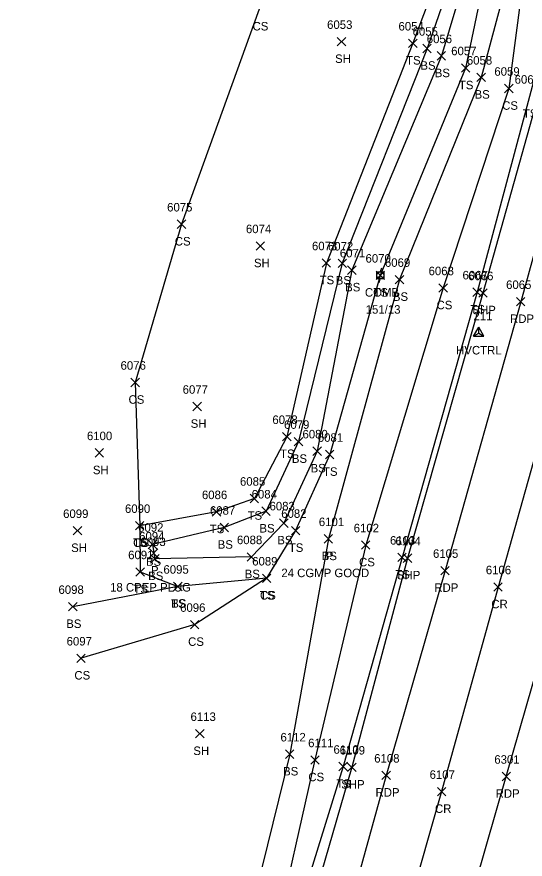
# Model space of a CAD drawing. Extents: x 1443912 to 1445411, y 621446 to 623693.
# Drawn here: x 1444411.3 to 1444530.8, y 621732.1 to 621930 of the extents above; entities that cross this region are included whole.
import ezdxf

# ---------------------------------------------------------------- set-up
doc = ezdxf.new("R2010")
doc.units = 0
for name, color, linetype in [('C_A', 7, 'Continuous'), ('C_I', 7, 'Continuous'), ('CPSM', 7, 'Continuous'), ('D_A', 7, 'Continuous'), ('D_C', 7, 'Continuous'), ('D_I', 7, 'Continuous'), ('D_TIC', 7, 'Continuous'), ('L_A', 7, 'Continuous'), ('L_I', 7, 'Continuous'), ('L_TIC', 7, 'Continuous'), ('LELB', 7, 'Continuous'), ('P_A', 7, 'Continuous'), ('P_I', 7, 'Continuous'), ('P_TIC', 7, 'Continuous'), ('PET', 7, 'Continuous'), ('PRC', 7, 'Continuous'), ('PSP', 7, 'Continuous'), ('U_A', 7, 'Continuous'), ('U_C', 7, 'Continuous'), ('U_I', 7, 'Continuous'), ('UP', 7, 'Continuous')]:
    doc.layers.add(name, color=color, linetype=linetype)

msp = doc.modelspace()

# ---------------------------------------------------------------- linework, layer by layer
at = {"layer": 'CPSM'}
for p, q in [((1444518.66, 621854.96), (1444519.91, 621857.13)), ((1444521.16, 621854.96), (1444519.91, 621857.13)), ((1444519.91, 621855.68), (1444519.91, 621857.13)), ((1444518.66, 621854.96), (1444519.91, 621855.68)), ((1444518.66, 621854.96), (1444521.16, 621854.96)), ((1444519.91, 621855.68), (1444519.91, 621855.68)), ((1444519.91, 621855.68), (1444521.16, 621854.96))]:
    msp.add_line(p, q, dxfattribs=at)
at = {"layer": 'D_TIC'}
for points in [[(1444483.56, 621806.34), (1444485.56, 621808.34)], [(1444485.56, 621806.34), (1444483.56, 621808.34)], [(1444442.45, 621802.96), (1444444.45, 621804.96)], [(1444444.45, 621802.96), (1444442.45, 621804.96)]]:
    msp.add_lwpolyline(points, dxfattribs=at)
at = {"layer": 'L_TIC'}
for points in [[(1444486.65, 621923.19), (1444488.65, 621925.19)], [(1444488.65, 621923.19), (1444486.65, 621925.19)], [(1444503.44, 621922.81), (1444505.44, 621924.81)], [(1444505.44, 621922.81), (1444503.44, 621924.81)], [(1444506.76, 621921.59), (1444508.76, 621923.59)], [(1444508.76, 621921.59), (1444506.76, 621923.59)], [(1444510.14, 621919.84), (1444512.14, 621921.84)], [(1444512.14, 621919.84), (1444510.14, 621921.84)], [(1444515.84, 621917), (1444517.84, 621919)], [(1444517.84, 621917), (1444515.84, 621919)], [(1444519.51, 621914.8), (1444521.51, 621916.8)], [(1444521.51, 621914.8), (1444519.51, 621916.8)], [(1444526, 621912.18), (1444528, 621914.18)], [(1444528, 621912.18), (1444526, 621914.18)], [(1444449.01, 621880.28), (1444451.01, 621882.28)], [(1444451.01, 621880.28), (1444449.01, 621882.28)], [(1444467.56, 621875.18), (1444469.56, 621877.18)], [(1444469.56, 621875.18), (1444467.56, 621877.18)], [(1444483.09, 621871.17), (1444485.09, 621873.17)], [(1444485.09, 621871.17), (1444483.09, 621873.17)], [(1444486.84, 621871.1), (1444488.84, 621873.1)], [(1444488.84, 621871.1), (1444486.84, 621873.1)], [(1444489.07, 621869.5), (1444491.07, 621871.5)], [(1444491.07, 621869.5), (1444489.07, 621871.5)], [(1444495.77, 621868.26), (1444497.77, 621870.26)], [(1444497.77, 621868.26), (1444495.77, 621870.26)], [(1444500.3, 621867.27), (1444502.3, 621869.27)], [(1444502.3, 621867.27), (1444500.3, 621869.27)], [(1444510.56, 621865.3), (1444512.56, 621867.3)], [(1444512.56, 621865.3), (1444510.56, 621867.3)], [(1444518.55, 621864.32), (1444520.55, 621866.32)], [(1444520.55, 621864.32), (1444518.55, 621866.32)], [(1444438.12, 621843.09), (1444440.12, 621845.09)], [(1444440.12, 621843.09), (1444438.12, 621845.09)], [(1444452.68, 621837.44), (1444454.68, 621839.44)], [(1444454.68, 621837.44), (1444452.68, 621839.44)], [(1444473.78, 621830.34), (1444475.78, 621832.34)], [(1444475.78, 621830.34), (1444473.78, 621832.34)], [(1444476.53, 621829.2), (1444478.53, 621831.2)], [(1444478.53, 621829.2), (1444476.53, 621831.2)], [(1444429.69, 621826.54), (1444431.69, 621828.54)], [(1444431.69, 621826.54), (1444429.69, 621828.54)], [(1444480.94, 621826.95), (1444482.94, 621828.95)], [(1444482.94, 621826.95), (1444480.94, 621828.95)], [(1444483.88, 621826.15), (1444485.88, 621828.15)], [(1444485.88, 621826.15), (1444483.88, 621828.15)], [(1444466.15, 621815.83), (1444468.15, 621817.83)], [(1444468.15, 621815.83), (1444466.15, 621817.83)], [(1444457.26, 621812.68), (1444459.26, 621814.68)], [(1444459.26, 621812.68), (1444457.26, 621814.68)], [(1444468.9, 621812.83), (1444470.9, 621814.83)], [(1444470.9, 621812.83), (1444468.9, 621814.83)], [(1444439.19, 621809.44), (1444441.19, 621811.44)], [(1444441.19, 621809.44), (1444439.19, 621811.44)], [(1444439.19, 621809.44), (1444441.19, 621811.44)], [(1444441.19, 621809.44), (1444439.19, 621811.44)], [(1444459.08, 621809.02), (1444461.08, 621811.02)], [(1444461.08, 621809.02), (1444459.08, 621811.02)], [(1444473.1, 621810.04), (1444475.1, 621812.04)], [(1444475.1, 621810.04), (1444473.1, 621812.04)], [(1444424.57, 621808.25), (1444426.57, 621810.25)], [(1444426.57, 621808.25), (1444424.57, 621810.25)], [(1444475.85, 621808.28), (1444477.85, 621810.28)], [(1444477.85, 621808.28), (1444475.85, 621810.28)], [(1444442.21, 621805.01), (1444444.21, 621807.01)], [(1444444.21, 621805.01), (1444442.21, 621807.01)], [(1444483.56, 621806.34), (1444485.56, 621808.34)], [(1444485.56, 621806.34), (1444483.56, 621808.34)], [(1444492.34, 621804.88), (1444494.34, 621806.88)], [(1444494.34, 621804.88), (1444492.34, 621806.88)], [(1444442.74, 621801.65), (1444444.74, 621803.65)], [(1444444.74, 621801.65), (1444442.74, 621803.65)], [(1444442.74, 621801.65), (1444444.74, 621803.65)], [(1444444.74, 621801.65), (1444442.74, 621803.65)], [(1444465.44, 621802.09), (1444467.44, 621804.09)], [(1444467.44, 621802.09), (1444465.44, 621804.09)], [(1444500.88, 621801.99), (1444502.88, 621803.99)], [(1444502.88, 621801.99), (1444500.88, 621803.99)], [(1444439.29, 621798.56), (1444441.29, 621800.56)], [(1444441.29, 621798.56), (1444439.29, 621800.56)], [(1444469.04, 621797.08), (1444471.04, 621799.08)], [(1444471.04, 621797.08), (1444469.04, 621799.08)], [(1444469.04, 621797.08), (1444471.04, 621799.08)], [(1444471.04, 621797.08), (1444469.04, 621799.08)], [(1444448.16, 621795.15), (1444450.16, 621797.15)], [(1444450.16, 621795.15), (1444448.16, 621797.15)], [(1444448.16, 621795.15), (1444450.16, 621797.15)], [(1444450.16, 621795.15), (1444448.16, 621797.15)], [(1444448.16, 621795.15), (1444450.16, 621797.15)], [(1444450.16, 621795.15), (1444448.16, 621797.15)], [(1444423.47, 621790.4), (1444425.47, 621792.4)], [(1444425.47, 621790.4), (1444423.47, 621792.4)], [(1444452.13, 621786.19), (1444454.13, 621788.19)], [(1444454.13, 621786.19), (1444452.13, 621788.19)], [(1444425.38, 621778.28), (1444427.38, 621780.28)], [(1444427.38, 621778.28), (1444425.38, 621780.28)], [(1444453.31, 621760.54), (1444455.31, 621762.54)], [(1444455.31, 621760.54), (1444453.31, 621762.54)], [(1444474.47, 621755.73), (1444476.47, 621757.73)], [(1444476.47, 621755.73), (1444474.47, 621757.73)], [(1444480.4, 621754.38), (1444482.4, 621756.38)], [(1444482.4, 621754.38), (1444480.4, 621756.38)], [(1444487.02, 621752.84), (1444489.02, 621754.84)], [(1444489.02, 621752.84), (1444487.02, 621754.84)]]:
    msp.add_lwpolyline(points, dxfattribs=at)
at = {"layer": 'LELB'}
for points in [[(1444632.65, 622301.98), (1444621.14, 622262.03), (1444607.9, 622216.16), (1444601.86, 622188.05), (1444585.99, 622134.3), (1444576.44, 622101.07), (1444565.66, 622076.68), (1444562.93, 622059.13), (1444545.54, 622046.15), (1444545.6, 622027.09), (1444542.78, 622003.02), (1444539.57, 621991.69), (1444533.95, 621966.13), (1444520.51, 621915.8), (1444501.3, 621868.27), (1444484.56, 621807.34), (1444475.47, 621756.73), (1444466.25, 621719.25), (1444448.38, 621716.17)], [(1444525.06, 622097.11), (1444514.69, 622074.67), (1444511.07, 622042.48), (1444501.15, 622010.66), (1444490.92, 621981.5), (1444468.29, 621931.82), (1444450.01, 621881.28), (1444439.12, 621844.09), (1444440.19, 621810.44)], [(1444574.55, 622074.53), (1444566.78, 622059.21), (1444562.93, 622059.13), (1444561.5, 622033.21), (1444553.8, 621993.71), (1444545.42, 621962.05), (1444531.89, 621911.31), (1444519.55, 621865.32), (1444501.88, 621802.99), (1444488.02, 621753.84), (1444471.78, 621701.48), (1444460.31, 621656.88), (1444459.55, 621655.45), (1444452.09, 621632.21), (1444445.68, 621624.35), (1444438.52, 621621.89)], [(1444527.32, 621968.25), (1444521.77, 621969.91), (1444504.44, 621923.81), (1444484.09, 621872.17), (1444474.78, 621831.34), (1444467.15, 621816.83), (1444458.26, 621813.68), (1444440.19, 621810.44), (1444440.29, 621799.56), (1444449.16, 621796.15)], [(1444525.1, 621967.65), (1444523.49, 621967.86), (1444507.76, 621922.59), (1444487.84, 621872.1), (1444477.53, 621830.2), (1444469.9, 621813.83), (1444460.08, 621810.02), (1444443.21, 621806.01), (1444443.74, 621802.65)], [(1444525.1, 621967.65), (1444511.14, 621920.84), (1444490.07, 621870.5), (1444481.94, 621827.95), (1444474.1, 621811.04), (1444466.44, 621803.09), (1444443.74, 621802.65)], [(1444527.32, 621968.25), (1444516.84, 621918), (1444496.77, 621869.26), (1444484.88, 621827.15), (1444476.85, 621809.28), (1444470.04, 621798.08), (1444449.16, 621796.15)], [(1444533.95, 621966.13), (1444527, 621913.18), (1444511.56, 621866.3), (1444493.34, 621805.88), (1444481.4, 621755.38), (1444471.56, 621711.89), (1444462.68, 621687.59)], [(1444470.04, 621798.08), (1444453.13, 621787.19), (1444426.38, 621779.28)], [(1444449.16, 621796.15), (1444424.47, 621791.4)]]:
    msp.add_lwpolyline(points, dxfattribs=at)
at = {"layer": 'P_TIC'}
for points in [[(1444519.92, 621864.12), (1444521.92, 621866.12)], [(1444521.92, 621864.12), (1444519.92, 621866.12)], [(1444528.8, 621862.07), (1444530.8, 621864.07)], [(1444530.8, 621862.07), (1444528.8, 621864.07)], [(1444502.16, 621801.82), (1444504.16, 621803.82)], [(1444504.16, 621801.82), (1444502.16, 621803.82)], [(1444510.99, 621798.88), (1444512.99, 621800.88)], [(1444512.99, 621798.88), (1444510.99, 621800.88)], [(1444523.46, 621795.02), (1444525.46, 621797.02)], [(1444525.46, 621795.02), (1444523.46, 621797.02)], [(1444489.06, 621752.65), (1444491.06, 621754.65)], [(1444491.06, 621752.65), (1444489.06, 621754.65)], [(1444497.16, 621750.76), (1444499.16, 621752.76)], [(1444499.16, 621750.76), (1444497.16, 621752.76)], [(1444525.41, 621750.49), (1444527.41, 621752.49)], [(1444527.41, 621750.49), (1444525.41, 621752.49)], [(1444510.19, 621746.94), (1444512.19, 621748.94)], [(1444512.19, 621746.94), (1444510.19, 621748.94)]]:
    msp.add_lwpolyline(points, dxfattribs=at)
at = {"layer": 'PET'}
for points in [[(1444707.78, 622511.05), (1444700.03, 622482.58), (1444691.73, 622453.67), (1444679.73, 622411.23), (1444667.69, 622368.84), (1444653.08, 622317.67), (1444637.74, 622256.92), (1444626.42, 622209.58), (1444619.02, 622182.67), (1444605.37, 622130.08), (1444589.4, 622078.61), (1444578.44, 622026.86), (1444565.52, 621990.05), (1444556.87, 621958.17), (1444542.16, 621907.74), (1444529.8, 621863.07), (1444511.99, 621799.88), (1444498.16, 621751.76), (1444483.13, 621697.3), (1444470.84, 621653.16), (1444463.41, 621627.34), (1444449.07, 621575.52), (1444430.26, 621508.83), (1444421.17, 621471.46)], [(1444444.37, 621464.94), (1444461.94, 621522.87), (1444475.59, 621570.55), (1444487.99, 621616.26), (1444502.92, 621667.73), (1444516.83, 621718.16), (1444526.41, 621751.49), (1444537.28, 621789.32), (1444558.59, 621865), (1444573.59, 621917.93), (1444597.58, 621998.81), (1444610.14, 622044.19), (1444623.48, 622089.5), (1444632.2, 622118.09)]]:
    msp.add_lwpolyline(points, dxfattribs=at)
at = {"layer": 'PRC'}
msp.add_lwpolyline([(1444618.32, 622127.38), (1444604.97, 622075.74), (1444590.11, 622023.77), (1444578.57, 621985.29), (1444569.73, 621954.72), (1444555.25, 621903.96), (1444542.35, 621859.58), (1444524.46, 621796.02), (1444511.19, 621747.94), (1444495.68, 621693.61), (1444483.2, 621649.28), (1444475.93, 621623.97), (1444461.82, 621572.2), (1444443.22, 621505.41), (1444432.75, 621467.94)], dxfattribs=at)
at = {"layer": 'PSP'}
msp.add_lwpolyline([(1444596.17, 622132.46), (1444585.6, 622096.58), (1444576.22, 622067.8), (1444567.15, 622029.85), (1444556.7, 621993.22), (1444548.18, 621960.88), (1444533.68, 621910.62), (1444520.92, 621865.12), (1444503.16, 621802.82), (1444490.06, 621753.65), (1444474.75, 621700.87), (1444461.97, 621656.27), (1444456.61, 621636.09), (1444438.52, 621570.3), (1444424.57, 621519.38), (1444411.29, 621473.11)], dxfattribs=at)
at = {"layer": 'UP'}
for p, q in [((1444495.94, 621868.43), (1444495.94, 621870.1)), ((1444495.94, 621870.1), (1444497.61, 621870.1)), ((1444497.02, 621870.93), (1444496.77, 621870.1)), ((1444497.61, 621870.1), (1444497.61, 621868.43)), ((1444497.61, 621868.43), (1444495.94, 621868.43)), ((1444496.52, 621867.6), (1444496.77, 621868.43)), ((1444496.77, 621869.26), (1444496.77, 621869.26))]:
    msp.add_line(p, q, dxfattribs=at)
msp.add_circle((1444496.77, 621869.26), 0.833, dxfattribs=at)

# ---------------------------------------------------------------- texts
at = {"layer": 'C_A'}
msp.add_text('HVCTRL', height=2, dxfattribs=at).set_placement((1444514.61, 621850.68))
at = {"layer": 'C_I'}
msp.add_text('211', height=2, dxfattribs=at).set_placement((1444518.68, 621858.68))
at = {"layer": 'D_A'}
for p in [(1444483.94, 621802.34), (1444442.83, 621798.96)]:
    msp.add_text('P', height=2, dxfattribs=at).set_placement(p)
at = {"layer": 'D_C'}
for s, p in [('24 CGMP GOOD', (1444473.5, 621798.34)), ('18 CPEP PLUG', (1444433.22, 621794.96))]:
    msp.add_text(s, height=2, dxfattribs=at).set_placement(p)
at = {"layer": 'D_I'}
for s, p in [('6101', (1444482.31, 621810.34)), ('6094', (1444440.06, 621806.96))]:
    msp.add_text(s, height=2, dxfattribs=at).set_placement(p)
at = {"layer": 'L_A'}
for s, p in [('CS', (1444466.73, 621926.82)), ('SH', (1444486.14, 621919.19)), ('TS', (1444502.85, 621918.81)), ('BS', (1444506.2, 621917.59)), ('BS', (1444509.58, 621915.84)), ('TS', (1444515.25, 621913)), ('BS', (1444518.95, 621910.8)), ('CS', (1444525.44, 621908.18)), ('TS', (1444530.3, 621906.31)), ('CS', (1444448.45, 621876.28)), ('SH', (1444467.05, 621871.18)), ('TS', (1444482.5, 621867.17)), ('BS', (1444486.28, 621867.1)), ('BS', (1444488.51, 621865.5)), ('TS', (1444495.18, 621864.26)), ('BS', (1444499.74, 621863.27)), ('CS', (1444510.01, 621861.3)), ('TS', (1444517.96, 621860.32)), ('CS', (1444437.56, 621839.09)), ('SH', (1444452.17, 621833.44)), ('TS', (1444473.19, 621826.34)), ('BS', (1444475.98, 621825.2)), ('SH', (1444429.17, 621822.54)), ('BS', (1444480.38, 621822.95)), ('TS', (1444483.29, 621822.15)), ('TS', (1444465.56, 621811.83)), ('TS', (1444456.67, 621808.68)), ('BS', (1444468.34, 621808.83)), ('TS', (1444438.6, 621805.44)), ('CS', (1444438.64, 621805.44)), ('BS', (1444458.53, 621805.02)), ('BS', (1444472.55, 621806.04)), ('SH', (1444424.06, 621804.25)), ('TS', (1444475.26, 621804.28)), ('BS', (1444441.65, 621801.01)), ('BS', (1444483, 621802.34)), ('CS', (1444491.78, 621800.88)), ('BS', (1444442.18, 621797.65)), ('BS', (1444442.18, 621797.65)), ('BS', (1444464.88, 621798.09)), ('TS', (1444500.29, 621797.99)), ('TS', (1444438.7, 621794.56)), ('TS', (1444468.45, 621793.08)), ('CS', (1444468.48, 621793.08)), ('TS', (1444447.57, 621791.15)), ('TS', (1444447.57, 621791.15)), ('BS', (1444447.6, 621791.15)), ('BS', (1444422.91, 621786.4)), ('CS', (1444451.57, 621782.19)), ('CS', (1444424.82, 621774.28)), ('SH', (1444452.8, 621756.54)), ('BS', (1444473.91, 621751.73)), ('CS', (1444479.85, 621750.38)), ('TS', (1444486.43, 621748.84))]:
    msp.add_text(s, height=2, dxfattribs=at).set_placement(p)
at = {"layer": 'L_I'}
for s, p in [('6053', (1444484.26, 621927.19)), ('6054', (1444501.05, 621926.81)), ('6055', (1444504.37, 621925.59)), ('6056', (1444507.7, 621923.84)), ('6057', (1444513.45, 621921)), ('6058', (1444517.13, 621918.8)), ('6059', (1444523.6, 621916.18)), ('6060', (1444528.37, 621914.31)), ('6075', (1444446.63, 621884.28)), ('6074', (1444465.17, 621879.18)), ('6073', (1444480.7, 621875.17)), ('6072', (1444484.46, 621875.1)), ('6071', (1444487.25, 621873.5)), ('6070', (1444493.3, 621872.26)), ('6069', (1444497.86, 621871.27)), ('6068', (1444508.13, 621869.3)), ('6067', (1444516.11, 621868.32)), ('6076', (1444435.68, 621847.09)), ('6077', (1444450.29, 621841.44)), ('6078', (1444471.39, 621834.34)), ('6079', (1444474.14, 621833.2)), ('6100', (1444427.78, 621830.54)), ('6080', (1444478.47, 621830.95)), ('6081', (1444482.07, 621830.15)), ('6085', (1444463.77, 621819.83)), ('6086', (1444454.82, 621816.68)), ('6084', (1444466.51, 621816.83)), ('6090', (1444436.72, 621813.44)), ('6090', (1444436.72, 621813.44)), ('6087', (1444456.7, 621813.02)), ('6083', (1444470.72, 621814.04)), ('6099', (1444422.17, 621812.25)), ('6082', (1444473.47, 621812.28)), ('6092', (1444439.82, 621809.01)), ('6101', (1444482.31, 621810.34)), ('6102', (1444490.52, 621808.88)), ('6093', (1444440.35, 621805.65)), ('6093', (1444440.35, 621805.65)), ('6088', (1444463.06, 621806.09)), ('6103', (1444499.06, 621805.99)), ('6091', (1444437.47, 621802.56)), ('6089', (1444466.64, 621801.08)), ('6089', (1444466.64, 621801.08)), ('6095', (1444445.77, 621799.15)), ('6095', (1444445.77, 621799.15)), ('6095', (1444445.77, 621799.15)), ('6098', (1444421.08, 621794.4)), ('6096', (1444449.69, 621790.19)), ('6097', (1444423, 621782.28)), ('6113', (1444452.14, 621764.54)), ('6112', (1444473.29, 621759.73)), ('6111', (1444479.8, 621758.38)), ('6110', (1444485.76, 621756.84))]:
    msp.add_text(s, height=2, dxfattribs=at).set_placement(p)
at = {"layer": 'P_A'}
for s, p in [('SHP', (1444518.45, 621860.12)), ('RDP', (1444527.29, 621858.07)), ('SHP', (1444500.69, 621797.82)), ('RDP', (1444509.48, 621794.88)), ('CR', (1444522.89, 621791.02)), ('SHP', (1444487.59, 621748.65)), ('RDP', (1444495.65, 621746.76)), ('RDP', (1444523.9, 621746.49)), ('CR', (1444509.63, 621742.94))]:
    msp.add_text(s, height=2, dxfattribs=at).set_placement(p)
at = {"layer": 'P_I'}
for s, p in [('6066', (1444517.43, 621868.12)), ('6065', (1444526.36, 621866.07)), ('6104', (1444500.34, 621805.82)), ('6105', (1444509.17, 621802.88)), ('6106', (1444521.59, 621799.02)), ('6109', (1444487.23, 621756.65)), ('6108', (1444495.34, 621754.76)), ('6301', (1444523.59, 621754.49)), ('6107', (1444508.37, 621750.94))]:
    msp.add_text(s, height=2, dxfattribs=at).set_placement(p)
at = {"layer": 'U_A'}
msp.add_text('COMB', height=2, dxfattribs=at).set_placement((1444493.16, 621864.26))
at = {"layer": 'U_C'}
msp.add_text('151/13', height=2, dxfattribs=at).set_placement((1444493.34, 621860.26))
at = {"layer": 'U_I'}
msp.add_text('6070', height=2, dxfattribs=at).set_placement((1444493.3, 621872.26))

doc.saveas('drawing.dxf')
